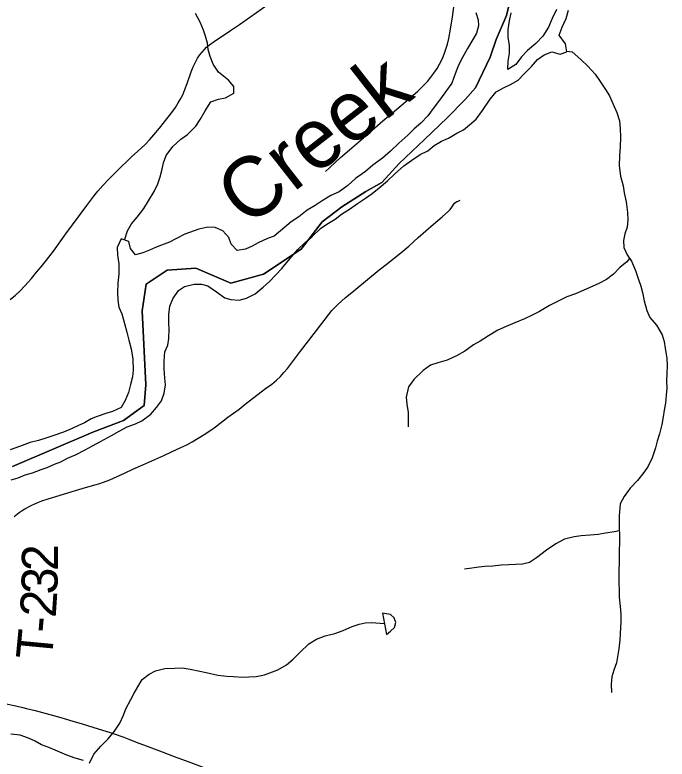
# Model space of a CAD drawing. Extents: x 0 to 34, y 0 to 22.
# Drawn here: x 7.268 to 8.296, y 14.754 to 15.927 of the extents above; entities that cross this region are included whole.
import ezdxf

# ---------------------------------------------------------------- set-up
doc = ezdxf.new("R2010")
doc.units = 0
for name, color, linetype in [('Default', 7, 'Continuous'), ('GM_X_County_Road', 7, 'Continuous'), ('GM_X_Major_River', 7, 'Continuous'), ('GM_X_Minor_Lake', 7, 'Continuous'), ('GM_X_Minor_River', 7, 'Continuous'), ('GM_X_Minor_River_Text', 7, 'Continuous'), ('GM_X_Township_Road', 7, 'Continuous'), ('GM_X_Township_Road_Text', 7, 'Continuous'), ('GM_X_US_Route', 7, 'Continuous')]:
    doc.layers.add(name, color=color, linetype=linetype)

msp = doc.modelspace()

# ---------------------------------------------------------------- linework, layer by layer
at = {"layer": 'Default'}
for points in [[(8.0499, 15.9547), (8.0431, 15.9261), (8.0272, 15.8886), (8.0175, 15.8606), (7.9942, 15.8124), (7.978, 15.7937), (7.9498, 15.765), (7.914, 15.7307), (7.8743, 15.6928), (7.8469, 15.6627), (7.8216, 15.6486), (7.7838, 15.6244), (7.7529, 15.601), (7.7199, 15.5579), (7.6602, 15.5183), (7.6086, 15.5042), (7.5534, 15.5279), (7.5085, 15.5247), (7.4753, 15.5025), (7.469, 15.4604), (7.475, 15.3437), (7.4721, 15.3116), (7.4396, 15.2875), (7.3913, 15.2694), (7.2647, 15.2153)], [(7.2647, 15.2153), (7.3913, 15.2694), (7.4396, 15.2875), (7.4721, 15.3116), (7.475, 15.3437), (7.469, 15.4604), (7.4753, 15.5025), (7.5085, 15.5247), (7.5534, 15.5279), (7.6086, 15.5042), (7.6602, 15.5183), (7.7199, 15.5579), (7.7529, 15.601), (7.7838, 15.6244), (7.8216, 15.6486), (7.8469, 15.6627), (7.8743, 15.6928), (7.914, 15.7307), (7.9498, 15.765), (7.978, 15.7937), (7.9942, 15.8124), (8.0175, 15.8606), (8.0272, 15.8886), (8.0431, 15.9261), (8.0499, 15.9547)]]:
    msp.add_lwpolyline(points, dxfattribs=at)
at = {"layer": 'GM_X_County_Road'}
msp.add_lwpolyline([(7.2611, 15.4783), (7.2696, 15.4855), (7.2769, 15.4922), (7.2842, 15.4998), (7.2948, 15.5118), (7.3027, 15.5214), (7.3097, 15.5301), (7.3183, 15.5407), (7.3295, 15.5548), (7.349, 15.582), (7.3818, 15.6266), (7.3931, 15.6414), (7.3994, 15.6492), (7.4071, 15.6582), (7.4165, 15.6681), (7.4332, 15.6849), (7.448, 15.699), (7.4525, 15.7033), (7.4672, 15.7166), (7.4743, 15.7235), (7.4811, 15.7307), (7.4877, 15.7382), (7.4963, 15.7487), (7.516, 15.7735), (7.5214, 15.7811), (7.526, 15.7883), (7.5291, 15.7937), (7.533, 15.8014), (7.5363, 15.8093), (7.54, 15.8192), (7.5464, 15.8374), (7.5495, 15.8455), (7.553, 15.8528), (7.5565, 15.8588), (7.5599, 15.8641), (7.5634, 15.8686), (7.5671, 15.8728), (7.5707, 15.8764), (7.575, 15.88), (7.5827, 15.8854), (7.6084, 15.9027), (7.6223, 15.9122), (7.6671, 15.9435)], dxfattribs=at)
at = {"layer": 'GM_X_Major_River'}
msp.add_lwpolyline([(7.3766, 14.7515), (7.3637, 14.7554), (7.3505, 14.7601), (7.332, 14.7679), (7.3218, 14.7722), (7.3105, 14.7765), (7.3004, 14.782), (7.2902, 14.787), (7.2766, 14.7917), (7.2622, 14.7934)], dxfattribs=at)
at = {"layer": 'GM_X_Minor_Lake'}
for points in [[(7.8478, 14.9842), (7.8541, 14.9506)], [(7.8541, 14.9506), (7.8606, 14.9555), (7.8668, 14.9615), (7.8688, 14.9694), (7.8663, 14.9767), (7.8606, 14.9821), (7.8478, 14.9842)]]:
    msp.add_lwpolyline(points, dxfattribs=at)
at = {"layer": 'GM_X_Minor_River'}
for points in [[(8.1218, 15.9355), (8.1151, 15.9215), (8.1096, 15.9079), (8.1007, 15.8936), (8.0895, 15.882), (8.0765, 15.8708), (8.0669, 15.8611), (8.058, 15.849), (8.0453, 15.8412), (8.0459, 15.8541), (8.048, 15.867), (8.0482, 15.8796), (8.0457, 15.8918), (8.0459, 15.9043), (8.048, 15.9179), (8.0504, 15.9304)], [(8.0495, 15.8173), (8.0614, 15.8243), (8.071, 15.8344), (8.0826, 15.846), (8.0922, 15.8569), (8.1026, 15.8643), (8.1147, 15.8687), (8.1276, 15.8655), (8.1386, 15.8688), (8.1362, 15.8817), (8.1261, 15.8952), (8.1309, 15.908), (8.1371, 15.9216), (8.1411, 15.9344)], [(7.4412, 15.5722), (7.4459, 15.5867), (7.4525, 15.5977), (7.4614, 15.6082), (7.4719, 15.6221), (7.4789, 15.6341), (7.4882, 15.6488), (7.494, 15.6609), (7.4972, 15.6718), (7.5004, 15.684), (7.5029, 15.6942), (7.5068, 15.7055), (7.5173, 15.7198), (7.5299, 15.731), (7.5407, 15.7388), (7.5534, 15.7515), (7.5607, 15.7625), (7.5685, 15.776), (7.5774, 15.7899), (7.5896, 15.7943), (7.6003, 15.7964), (7.6133, 15.8039), (7.6138, 15.8145), (7.6052, 15.8241), (7.5895, 15.8369), (7.581, 15.8495), (7.5762, 15.8614), (7.5733, 15.8728), (7.572, 15.8827), (7.5691, 15.8934), (7.5658, 15.9029), (7.5607, 15.9155), (7.5529, 15.9293)], [(7.9951, 15.9309), (7.9987, 15.9194), (7.9993, 15.9099), (7.9961, 15.8986), (7.9903, 15.8884), (7.9817, 15.8741), (7.9739, 15.8601), (7.9677, 15.8481), (7.9626, 15.8345), (7.9571, 15.8197), (7.9485, 15.8081), (7.9392, 15.7949), (7.9276, 15.7795), (7.9195, 15.7682), (7.9084, 15.7566), (7.898, 15.7477), (7.8876, 15.7376), (7.8734, 15.7252), (7.8603, 15.7121), (7.848, 15.7013), (7.8327, 15.6901), (7.8212, 15.6804), (7.8055, 15.6692), (7.7932, 15.658), (7.7794, 15.6483), (7.7664, 15.6425), (7.7526, 15.6343), (7.7415, 15.6269), (7.7293, 15.6191)], [(8.1384, 15.8698), (8.147, 15.869), (8.1605, 15.857), (8.1717, 15.8462), (8.1829, 15.8339), (8.1896, 15.824), (8.1992, 15.8094), (8.2055, 15.7994), (8.2132, 15.783), (8.2169, 15.7734), (8.2216, 15.7601), (8.2226, 15.7479), (8.2228, 15.7342), (8.2225, 15.7194), (8.2212, 15.7057), (8.221, 15.6894), (8.223, 15.673), (8.227, 15.6578), (8.2287, 15.6468), (8.2319, 15.6323), (8.2339, 15.6159), (8.2345, 15.6041), (8.2332, 15.5927), (8.23, 15.5818), (8.2276, 15.5716), (8.2282, 15.5605), (8.2333, 15.5491), (8.24, 15.5387), (8.2466, 15.5242), (8.251, 15.5116), (8.255, 15.4997), (8.2575, 15.4895), (8.2603, 15.4765), (8.2643, 15.4609), (8.2694, 15.4502), (8.2795, 15.4382), (8.2884, 15.4229), (8.2916, 15.4122), (8.2934, 15.4019), (8.2958, 15.3856), (8.2964, 15.3742), (8.2962, 15.362), (8.2956, 15.3495), (8.2959, 15.3389), (8.2949, 15.3275), (8.2936, 15.3153), (8.2919, 15.304), (8.2903, 15.2934), (8.2882, 15.2812), (8.2842, 15.2665), (8.2806, 15.2551), (8.2782, 15.2445), (8.273, 15.229), (8.2664, 15.2158), (8.2598, 15.2057), (8.2498, 15.1933), (8.2382, 15.1813), (8.2289, 15.1681), (8.2223, 15.1561), (8.2209, 15.1375), (8.2206, 15.1212), (8.2211, 15.1041), (8.2202, 15.0422), (8.2205, 15.0319), (8.2207, 15.0201), (8.2209, 15.0091), (8.2222, 14.9947), (8.2235, 14.9825), (8.2234, 14.9711), (8.2223, 14.9514), (8.2218, 14.9419), (8.2201, 14.9275), (8.2184, 14.9153), (8.2167, 14.9059), (8.2124, 14.8941), (8.2092, 14.8836), (8.2083, 14.8718), (8.2088, 14.8589)], [(7.2624, 15.194), (7.2738, 15.1973), (7.2845, 15.2021), (7.2963, 15.2053), (7.31, 15.2104), (7.3195, 15.2137), (7.331, 15.2189), (7.3409, 15.2225), (7.3512, 15.2284), (7.3642, 15.2336), (7.3791, 15.2417), (7.3906, 15.248), (7.4035, 15.2546), (7.4207, 15.2642), (7.433, 15.2709), (7.4456, 15.2776), (7.4586, 15.2827), (7.4685, 15.2871), (7.4827, 15.2979), (7.4915, 15.308), (7.4993, 15.3186), (7.5036, 15.331), (7.5057, 15.3439), (7.5047, 15.3546), (7.5038, 15.369), (7.5036, 15.3815), (7.5046, 15.396), (7.5093, 15.4065), (7.5113, 15.4171), (7.5115, 15.4316), (7.5109, 15.4411), (7.5111, 15.4547), (7.5125, 15.468), (7.5176, 15.4797), (7.5261, 15.4929), (7.5357, 15.4988), (7.5509, 15.5028), (7.5626, 15.5026), (7.5725, 15.5002), (7.586, 15.4905), (7.5991, 15.4812), (7.6089, 15.4784), (7.6222, 15.4774), (7.6336, 15.4807), (7.6473, 15.4873), (7.66, 15.4981), (7.67, 15.5071), (7.6796, 15.5176), (7.6893, 15.5273), (7.702, 15.5427), (7.7143, 15.5574), (7.7255, 15.5678), (7.737, 15.5779), (7.7501, 15.5903), (7.76, 15.597), (7.7731, 15.6051), (7.7834, 15.613), (7.796, 15.6211), (7.8083, 15.6297), (7.8213, 15.6382), (7.8313, 15.6457), (7.8424, 15.6546), (7.8558, 15.6655), (7.867, 15.6763), (7.8812, 15.6894), (7.8942, 15.698), (7.9073, 15.7073), (7.9191, 15.7128), (7.9291, 15.7214), (7.9409, 15.728), (7.9516, 15.7328), (7.965, 15.7406), (7.9753, 15.7462), (7.9849, 15.7536), (7.9957, 15.7626), (8.0057, 15.7765), (8.0174, 15.7945), (8.027, 15.8058), (8.0396, 15.8125), (8.0495, 15.8173)], [(7.7293, 15.6191), (7.7159, 15.6086), (7.704, 15.6008), (7.6771, 15.5784), (7.6668, 15.5744), (7.6519, 15.5678), (7.6424, 15.5626), (7.6321, 15.5578), (7.6188, 15.5557), (7.6091, 15.5657), (7.6058, 15.576), (7.5961, 15.5868), (7.584, 15.5919), (7.5727, 15.5925), (7.5582, 15.5893), (7.5361, 15.5816), (7.522, 15.5739), (7.512, 15.5691), (7.4998, 15.5639), (7.4903, 15.5603), (7.4807, 15.5562), (7.4701, 15.5522), (7.4587, 15.549), (7.4508, 15.5589), (7.448, 15.57), (7.4359, 15.574), (7.4296, 15.5604), (7.4302, 15.5486), (7.4323, 15.5345), (7.4324, 15.5186), (7.4307, 15.5045), (7.4301, 15.4894), (7.4307, 15.4772), (7.4324, 15.4665), (7.4368, 15.4558), (7.4411, 15.4406), (7.4447, 15.4272), (7.448, 15.4143), (7.4516, 15.4009), (7.4544, 15.3842), (7.4549, 15.3671), (7.4536, 15.3564), (7.4507, 15.3443), (7.4475, 15.3318), (7.4424, 15.319), (7.4358, 15.3081), (7.4224, 15.3018), (7.4118, 15.2986), (7.3984, 15.2942), (7.3889, 15.2902), (7.3782, 15.2842), (7.3686, 15.2798), (7.3587, 15.275), (7.345, 15.2692), (7.3282, 15.2633), (7.3172, 15.2597), (7.3057, 15.2564), (7.2928, 15.2528), (7.2756, 15.247), (7.2612, 15.2415)], [(8.237, 15.5433), (8.2328, 15.5381), (8.222, 15.5287), (8.212, 15.5186), (8.2009, 15.51), (8.1887, 15.5037), (8.1784, 15.499), (8.165, 15.4931), (8.152, 15.4876), (8.1383, 15.4828), (8.1246, 15.4758), (8.1112, 15.4692), (8.0951, 15.4595), (8.0825, 15.4532), (8.0715, 15.4481), (8.0562, 15.4415), (8.0428, 15.436), (8.0295, 15.4301), (8.015, 15.4212), (8.0019, 15.4126), (7.9912, 15.4071), (7.9774, 15.397), (7.9644, 15.3896), (7.9499, 15.383), (7.9351, 15.3787), (7.9233, 15.375), (7.9118, 15.3668), (7.8972, 15.3526), (7.889, 15.341), (7.8854, 15.3247), (7.8864, 15.3137), (7.8881, 15.3003), (7.8883, 15.2905), (7.8881, 15.2775)], [(8.2209, 15.1139), (8.2137, 15.1121), (8.1992, 15.1101), (8.1878, 15.108), (8.1753, 15.107), (8.1609, 15.1061), (8.1499, 15.1043), (8.1346, 15.1004), (8.1209, 15.0934), (8.1063, 15.0833), (8.0906, 15.071), (8.0795, 15.064), (8.0685, 15.0611), (8.0575, 15.0605), (8.0472, 15.0602), (8.0351, 15.0597), (8.0218, 15.0583), (8.0093, 15.0574), (7.9994, 15.0564), (7.9887, 15.055), (7.9773, 15.0533)], [(7.3861, 14.7477), (7.3929, 14.7618), (7.4041, 14.7742), (7.4153, 14.7861), (7.4257, 14.7978), (7.4338, 14.8106), (7.4397, 14.8234), (7.4432, 14.8332), (7.4511, 14.8479), (7.4565, 14.8581), (7.462, 14.8679), (7.4693, 14.8792), (7.4801, 14.8877), (7.49, 14.8929), (7.5049, 14.8969), (7.52, 14.8974), (7.5322, 14.8976), (7.5447, 14.8959), (7.5598, 14.8926), (7.57, 14.8906), (7.5885, 14.8865), (7.6025, 14.8848), (7.6127, 14.8843), (7.6275, 14.8833), (7.637, 14.8835), (7.6488, 14.8841), (7.6621, 14.887), (7.6827, 14.8946), (7.6964, 14.9024), (7.7068, 14.9114), (7.7176, 14.9222), (7.7318, 14.9357), (7.744, 14.9431), (7.7574, 14.9482), (7.7726, 14.9518), (7.7856, 14.9566), (7.8001, 14.9632), (7.8111, 14.9665), (7.8206, 14.9686), (7.8305, 14.9692), (7.8509, 14.9676)]]:
    msp.add_lwpolyline(points, dxfattribs=at)
at = {"layer": 'GM_X_Township_Road'}
for points in [[(7.758, 15.6803), (7.7648, 15.6867), (7.7819, 15.7021), (7.796, 15.7143), (7.8181, 15.7334), (7.8316, 15.7453), (7.8485, 15.76), (7.8636, 15.773), (7.8774, 15.7845), (7.8959, 15.8002), (7.9033, 15.8068), (7.9113, 15.8146), (7.9185, 15.8224), (7.9241, 15.829), (7.929, 15.8354), (7.9338, 15.8427), (7.9379, 15.8496), (7.9418, 15.8574), (7.9452, 15.8654), (7.9479, 15.873), (7.9503, 15.8808), (7.9524, 15.8898), (7.955, 15.9045), (7.958, 15.9242), (7.9621, 15.955)], [(7.2674, 15.1362), (7.2751, 15.1425), (7.2801, 15.146), (7.2843, 15.1486), (7.2941, 15.1539), (7.3009, 15.157), (7.3107, 15.1609), (7.3207, 15.1644), (7.3385, 15.1697), (7.3534, 15.174), (7.3745, 15.1803), (7.3944, 15.1865), (7.4022, 15.1885), (7.4081, 15.1905), (7.4179, 15.1943), (7.4411, 15.2048), (7.4546, 15.2111), (7.4699, 15.2179), (7.4842, 15.224), (7.5033, 15.2328), (7.5151, 15.2384), (7.5299, 15.245), (7.5394, 15.2495), (7.5481, 15.2543), (7.5666, 15.2656), (7.5771, 15.2723), (7.5846, 15.2778), (7.6042, 15.293), (7.6217, 15.3058), (7.6315, 15.3133), (7.6633, 15.338), (7.6732, 15.345), (7.6809, 15.3513), (7.6871, 15.3573), (7.6926, 15.3632), (7.6982, 15.3699), (7.7188, 15.3971), (7.7439, 15.4295), (7.7625, 15.4544), (7.768, 15.4611), (7.773, 15.4665), (7.7779, 15.4712), (7.7892, 15.4809), (7.8025, 15.4921), (7.806, 15.4946), (7.8427, 15.525), (7.8557, 15.5355), (7.8798, 15.5545), (7.8892, 15.5626), (7.9038, 15.5761), (7.9281, 15.5973), (7.9419, 15.6089), (7.9516, 15.6176), (7.9543, 15.6202), (7.9571, 15.6242), (7.9592, 15.6274), (7.9615, 15.6303), (7.9633, 15.6319), (7.9649, 15.6329), (7.966, 15.6332), (7.97, 15.6352)]]:
    msp.add_lwpolyline(points, dxfattribs=at)
at = {"layer": 'GM_X_US_Route'}
for points in [[(7.2132, 14.8498), (7.2378, 14.8447), (7.2549, 14.8413), (7.2701, 14.838), (7.281, 14.8353)], [(7.281, 14.8353), (7.287, 14.8339), (7.3002, 14.8304), (7.312, 14.8274), (7.341, 14.8194), (7.3543, 14.8155), (7.3744, 14.8094), (7.3999, 14.8016), (7.4189, 14.7956), (7.4248, 14.7937), (7.44, 14.7883), (7.4482, 14.7852), (7.4598, 14.7807), (7.4754, 14.7747), (7.5004, 14.7652), (7.5195, 14.7581), (7.5482, 14.7475), (7.5882, 14.7321), (7.6049, 14.7254), (7.6165, 14.7204)]]:
    msp.add_lwpolyline(points, dxfattribs=at)

# ---------------------------------------------------------------- texts
at = {"layer": 'GM_X_Minor_River_Text'}
msp.add_text('Creek', height=0.09469, rotation=38.0024, dxfattribs=at).set_placement((7.6348, 15.5902))
at = {"layer": 'GM_X_Township_Road_Text'}
for s, rotation, p in [('2', 90.3202, (7.3364, 15.0505)), ('3', 87.9919, (7.3351, 15.013)), ('2', 86.1886, (7.3327, 14.9761)), ('-', 84.984, (7.3306, 14.9516)), ('T', 84.5576, (7.3265, 14.9088))]:
    msp.add_text(s, height=0.0568, rotation=rotation, dxfattribs=at).set_placement(p)

doc.saveas('drawing.dxf')
